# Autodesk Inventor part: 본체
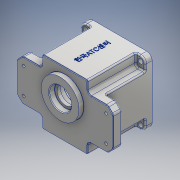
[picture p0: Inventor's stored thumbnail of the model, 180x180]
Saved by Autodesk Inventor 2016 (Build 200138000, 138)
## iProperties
Created: 2017-01
Part Number: 본체
Material: 알루미늄 6061
Document SubType Name: Modeling
Designer: Owner
Mass: 876.818 g
Surface Area: 765.633 cm^2
Volume: 324.747 cm^3
Density: 2.7 g/cm^3
Appearance: 알루미늄 - 평지
Author: Owner
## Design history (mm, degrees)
sketch "스케치1"
  geometry: L1 (70, -30)-(-70, -30); L2 (-70, -30)-(-70, 30); L3 (-70, 30)-(70, 30); L4 (70, 30)-(70, -30); L5 (70, -30)-(-70, 30); L6 (-70, -30)-(70, 30); 1 further point
  constraints: 12 end point, 2 midpoint, 2 parallel, 1 horizontal, 1 perpendicular
  dimensions: "d0" = 140 distance of L2.end L3.end; "d1" = 60 distance of L1.end L2.end
extrude "돌출1" new body sketch "스케치1" distance "d2" = 13; taper "d3" = 0 deg
sketch "스케치2"
  geometry: L1 (-47, -47)-(47, -47); L2 (47, -47)-(47, 47); L3 (47, 47)-(-47, 47); L4 (-47, 47)-(-47, -47); L5 (-47, -47)-(47, 47); L6 (47, -47)-(-47, 47); 1 further point
  constraints: 12 end point, 2 midpoint, 2 parallel, 1 horizontal, 1 perpendicular
  dimensions: "d4" = 94 distance of L3.end L2.end; "d5" = 94 distance of L2.end L1.end
extrude "돌출2" join sketch "스케치2" distance "d6" = 80; taper "d7" = 0 deg
sketch "스케치3"
  geometry: L1 (-47, 30)-(-33, 30); L2 (-33, 30)-(-33, 47); L3 (-33, 47)-(-47, 47); L4 (-47, 47)-(-47, 30); L5 (-47, 30)-(-33, 47); L6 (-33, 30)-(-47, 47); 3 further points
  constraints: 12 end point, 2 midpoint, 2 parallel, 1 coincident, 1 horizontal, 1 perpendicular
  dimensions: "d8" = 14 distance of L2.end L3.end; "d9" = 17 distance of L3.end L1.start
extrude "돌출3" cut sketch "스케치3" distance "d10" = 70; taper "d11" = 0 deg
sketch "스케치4"
  geometry: L1 (0, 0)-(80, 0); L2 (80, -47)-(80, 47) reference; L3 (80, 0)-(80, 43); L4 (71, 43)-(71, 40); L5 (71, 40)-(9, 40); L6 (9, 40)-(9, 0); L7 (71, 43)-(80, 43)
  constraints: 12 end point, 3 perpendicular, 2 point on line, 1 midpoint
  dimensions: "d12" = 86 diameter of L7 L1; "d13" = 80 diameter of L5 L1; "d14" = 9 distance of L4.start L3.end; "d15" = 71 distance between parallel lines of L2 L6
revolve "회전2" sketch "스케치4" stored, may be unused: angle "d17" = 90 deg
sketch "스케치5"
  geometry: A1 r 21 centre (0, -11) between (-8.978, 7.984) and (8.978, 7.984); A2 r 15 centre (0, 20) between (8.978, 7.984) and (-8.978, 7.984); 1 further point
  constraints: 4 point on circle, 2 centre point, 2 vertical alignment
  dimensions: "d18" = 11 distance of A1.centre point (0, 0); "d19" = 20 distance of point (0, 0) A2.centre; "d20" = 42 diameter of A1; "d21" = 30 diameter of A2
extrude "돌출4" join sketch "스케치5" distance "d22" = 7; taper "d23" = 0 deg
sketch "스케치6"
  geometry: A1 r 4 centre (36, 0) between (35.852, 3.997) and (35.852, -3.997); A2 r 40 centre (0, 0) between (39.148, -8.214) and (39.148, 8.214) reference; A3 r 3.5 centre (35.722, -7.495) between (39.148, -8.214) and (35.852, -3.997); A4 r 3.5 centre (35.722, 7.495) between (35.852, 3.997) and (39.148, 8.214); 1 further point
  constraints: 8 point on circle, 4 tangent, 3 centre point, 1 horizontal alignment
  dimensions: "d24" = 8 diameter of A1; "d25" = 36 distance of point (0, 0) A1.centre; "d28" = 7 diameter of A3; "d29" = 7 diameter of A4
extrude "돌출6" join sketch "스케치6" stored distance "d30" = 7; taper "d31" = 0 deg
hole "구멍1" diameter "d34" = 19; stored, may be unused: countersink angle "d38" = 90 deg, drill point angle "d40" = 0 deg; dims "d32" = 10, "d33" = 10, "d35" = 6, "d36" = 22, "d37" = 7, "d39" = 8
hole "구멍2" diameter "d43" = 25; stored, may be unused: countersink angle "d47" = 90 deg, drill point angle "d49" = 0 deg; dims "d41" = 10, "d42" = 10, "d44" = 6, "d45" = 35, "d46" = 10, "d48" = 8
sketch "스케치7"
  geometry: C1 r 27.5 at (0, 11); C2 r 12.5 at (0, 11) reference; 1 further point
  constraints: 1 centre point, 1 concentric
  dimensions: "d50" = 55 diameter of C1
extrude "돌출7" join sketch "스케치7" distance "d51" = 7; taper "d52" = 0 deg
hole "구멍3" diameter "d55" = 32; stored, may be unused: countersink angle "d59" = 90 deg, drill point angle "d61" = 0 deg; dims "d56" = 6, "d57" = 35, "d58" = 10, "d60" = 8, "d126" = 10, "d127" = 10
fillet "모깎기1" dims "d62" = 8
sketch "스케치8"
  geometry: 2 further points
  dimensions: "d63" = 40 horizontal distance of point (40, 40) point (0, 0); "d64" = 40 horizontal distance of point (0, 0) point (40, 40)
hole "구멍4" sketch "스케치8" at (40, 40) diameter "d65" = 7; stored, may be unused: countersink angle "d69" = 90 deg, drill point angle "d71" = 0 deg; dims "d66" = 6, "d67" = 35, "d68" = 10, "d70" = 7
sketch "스케치9"
  geometry: 2 further points
  dimensions: "d78" = 19 vertical distance of point (0, 0) point (60, 19); "d79" = 60 horizontal distance of point (0, 0) point (60, 19)
hole "구멍5" sketch "스케치9" at (60, 19) diameter "d80" = 4; stored, may be unused: countersink angle "d84" = 90 deg, drill point angle "d86" = 0 deg; dims "d81" = 6, "d82" = 10, "d83" = 4, "d85" = 7
chamfer "모따기1" distance "d93" = 1; stored, may be unused: second distance "d94" = 2, angle "d95" = 45 deg
hole "구멍6" diameter "d98" = 3.242; stored, may be unused: countersink angle "d102" = 90 deg, drill point angle "d104" = 118 deg; dims "d96" = 10, "d97" = 10, "d99" = 7, "d100" = 10, "d101" = 4, "d103" = 9
fillet "모깎기2" dims "d105" = 3
fillet "모깎기3" dims "d106" = 2
fillet "모깎기4" dims "d107" = 2
fillet "모깎기5" dims "d108" = 0.3
chamfer "모따기2" distance "d109" = 1; stored, may be unused: second distance "d110" = 2, angle "d111" = 45 deg
chamfer "모따기3" distance "d112" = 8; stored, may be unused: second distance "d113" = 2, angle "d114" = 45 deg
fillet "모깎기6" dims "d115" = 5
fillet "모깎기7" dims "d116" = 5
fillet "모깎기9" dims "d118" = 2
fillet "모깎기10" dims "d119" = 2
fillet "모깎기8" dims "d117" = 2
sketch "스케치10"
  geometry: L1 (-31, -47)-(31, -47) reference; L2 (33, -45)-(33, -35) reference; L3 (38, -30)-(59.929, -30) reference; L4 (68.536, -23.464)-(63.464, -28.536) reference; L5 (70, -19.929)-(70, 19.929) reference; L6 (63.464, 28.536)-(68.536, 23.464) reference; L7 (59.929, 30)-(38, 30) reference; L8 (33, 35)-(33, 45) reference; L9 (31, 47)-(-31, 47) reference; L10 (-33, 45)-(-33, 35) reference; L11 (-38, 30)-(-59.929, 30) reference; L12 (-68.536, 23.464)-(-63.464, 28.536) reference; L13 (-70, 19.929)-(-70, -19.929) reference; L14 (-63.464, -28.536)-(-68.536, -23.464) reference; L15 (-59.929, -30)-(-38, -30) reference; L16 (-33, -35)-(-33, -45) reference; L17 (-31, 46)-(31, 46); L18 (32, 45)-(32, 35); L19 (38, 29)-(59.929, 29); L20 (62.757, 27.828)-(67.828, 22.757); L21 (69, 19.929)-(69, -19.929); L22 (67.828, -22.757)-(62.757, -27.828); L23 (59.929, -29)-(38, -29); L24 (32, -35)-(32, -45); L25 (31, -46)-(-31, -46); L26 (-32, -45)-(-32, -35); L27 (-38, -29)-(-59.929, -29); L28 (-62.757, -27.828)-(-67.828, -22.757); L29 (-69, -19.929)-(-69, 19.929); L30 (-67.828, 22.757)-(-62.757, 27.828); L31 (-59.929, 29)-(-38, 29); L32 (-32, 35)-(-32, 45); C1 r 2 at (60, -19) reference; C2 r 2 at (-60, -19) reference; C3 r 2 at (60, 19) reference; C4 r 2 at (-60, 19) reference; C5 r 27.8 at (0, 11) reference; A1 r 2 centre (-31, -45) between (-33, -45) and (-31, -47) reference; A2 r 2 centre (31, -45) between (31, -47) and (33, -45) reference; A3 r 5 centre (38, -35) between (38, -30) and (33, -35) reference; A4 r 5 centre (59.929, -25) between (59.929, -30) and (63.464, -28.536) reference; A5 r 5 centre (65, -19.929) between (68.536, -23.464) and (70, -19.929) reference; A6 r 5 centre (65, 19.929) between (70, 19.929) and (68.536, 23.464) reference; A7 r 5 centre (59.929, 25) between (63.464, 28.536) and (59.929, 30) reference; A8 r 5 centre (38, 35) between (33, 35) and (38, 30) reference; A9 r 2 centre (31, 45) between (33, 45) and (31, 47) reference; A10 r 2 centre (-31, 45) between (-31, 47) and (-33, 45) reference; A11 r 5 centre (-38, 35) between (-38, 30) and (-33, 35) reference; A12 r 5 centre (-59.929, 25) between (-59.929, 30) and (-63.464, 28.536) reference; A13 r 5 centre (-65, 19.929) between (-68.536, 23.464) and (-70, 19.929) reference; A14 r 5 centre (-65, -19.929) between (-70, -19.929) and (-68.536, -23.464) reference; A15 r 5 centre (-59.929, -25) between (-63.464, -28.536) and (-59.929, -30) reference; A16 r 5 centre (-38, -35) between (-33, -35) and (-38, -30) reference; A17 r 1 centre (31, 45) between (32, 45) and (31, 46); A18 r 6 centre (38, 35) between (32, 35) and (38, 29); A19 r 4 centre (59.929, 25) between (62.757, 27.828) and (59.929, 29); A20 r 4 centre (65, 19.929) between (69, 19.929) and (67.828, 22.757); A21 r 4 centre (65, -19.929) between (67.828, -22.757) and (69, -19.929); A22 r 4 centre (59.929, -25) between (59.929, -29) and (62.757, -27.828); A23 r 6 centre (38, -35) between (38, -29) and (32, -35); A24 r 1 centre (31, -45) between (31, -46) and (32, -45); A25 r 1 centre (-31, -45) between (-32, -45) and (-31, -46); A26 r 6 centre (-38, -35) between (-32, -35) and (-38, -29); A27 r 4 centre (-59.929, -25) between (-62.757, -27.828) and (-59.929, -29); A28 r 4 centre (-65, -19.929) between (-69, -19.929) and (-67.828, -22.757); A29 r 4 centre (-65, 19.929) between (-67.828, 22.757) and (-69, 19.929); A30 r 4 centre (-59.929, 25) between (-59.929, 29) and (-62.757, 27.828); A31 r 6 centre (-38, 35) between (-38, 29) and (-32, 35); A32 r 1 centre (-31, 45) between (-31, 46) and (-32, 45); 1 further point
  constraints: 32 end point, 32 point on circle, 16 centre point, 31 other
  dimensions: "d120" = 1 distance between parallel lines of L9 L17
extrude "돌출8" cut sketch "스케치10" distance "d121" = 1; taper "d122" = 0 deg
sketch "스케치11"
  geometry: L1 (0, 0)-(78, 0) reference; 2 further points
  constraints: 1 vertical alignment, 1 other
  dimensions: "d123" = 40 distance from line of L1 point (39, -40)
feature "엠보싱1" sketch "스케치11" dims "d8" = 14, "d9" = 17, "d124" = 0.5, "d125" = 0
node "솔리드1"
mirror "대칭1"
mirror "대칭2"
mirror "대칭3"
pattern_linear "직사각형 패턴1" dims "d74" = 80
pattern_linear "직사각형 패턴2" dims "d89" = 120, "d92" = 38
mirror "대칭4"
node "투영된 루프1"
